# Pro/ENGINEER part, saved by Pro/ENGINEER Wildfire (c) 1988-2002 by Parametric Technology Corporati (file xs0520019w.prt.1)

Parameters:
  HERSTELLER = "Hersteller"
  PSOL_NOTUSEDSKLST = "SKLST{SKETCH{NAME{"Sketch 37"}MAT{1,0,0,0,0,1,0,0,0,0,1,0,0,0,0,1}SKETCHON{"
  NB = "XS0520019w"
  NN = "XS-Series -Wheel"
  NT = "Thermoplastic Elastomer (x-tra Soft )"
  NBSYN = "$PN.w"
  LINA = "XS0520019w"
  PN = "XS0520019"
  DIA = "5"
  D = "5.000"
  WIDTH = "2"
  W = "2.000"
  HUB = "2-3/16"
  H = "2.188"
  BORE = "1-3/16"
